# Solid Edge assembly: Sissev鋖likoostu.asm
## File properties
Author: Türk
Template: Iso Assembly.asm
Last saved by: Türk
Revision: 15
Application: Solid Edge
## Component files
ll.par
1k_R45.par
2k_R40.par
3k_R36.par
4k_R30.par
5k_R20.par
li.par
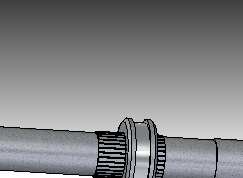
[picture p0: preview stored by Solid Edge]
